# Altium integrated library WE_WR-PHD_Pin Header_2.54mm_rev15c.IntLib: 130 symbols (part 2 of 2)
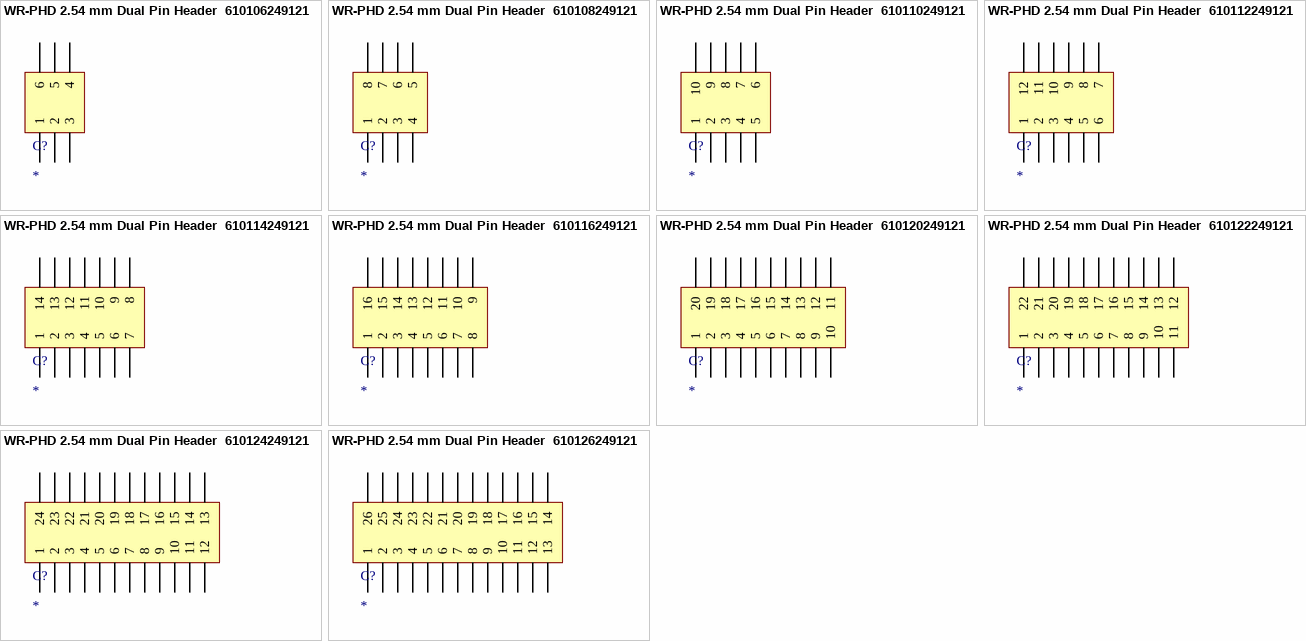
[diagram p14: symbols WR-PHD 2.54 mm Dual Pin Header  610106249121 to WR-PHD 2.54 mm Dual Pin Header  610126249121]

## WR-PHD 2.54 mm Dual Pin Header  610124249121
designator C?
WR-PHD 2.54 mm Dual Pin Header; Manufacturer: Würth Elektronik eiSos GmbH; partNo: 610124249121; ComponentLink1 Description: Manufacturer; ComponentLink2 Description: Datasheet; NoPins: 24
footprint 610124249121
pins: 1, 2, 3, 4, 5, 6, 7, 8, 9, 10, 11, 12, 13, 14, 15, 16, 17, 18, 19, 20, 21, 22, 23, 24

## WR-PHD 2.54 mm Dual Pin Header  610126249121
designator C?
WR-PHD 2.54 mm Dual Pin Header; Manufacturer: Würth Elektronik eiSos GmbH; partNo: 610126249121; ComponentLink1 Description: Manufacturer; ComponentLink2 Description: Datasheet; NoPins: 26
footprint 610126249121
pins: 1, 2, 3, 4, 5, 6, 7, 8, 9, 10, 11, 12, 13, 14, 15, 16, 17, 18, 19, 20, 21, 22, 23, 24, 25, 26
